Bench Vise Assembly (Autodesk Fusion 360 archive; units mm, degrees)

design "Bench Vice Assembly" references "Handle Bar", "Jaw Screw", "Vice Nut", "Base", "Nut", "Fixed Jaw", "Sliding Jaw", "Jaw Plate"
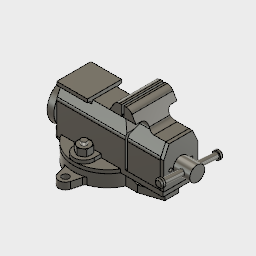
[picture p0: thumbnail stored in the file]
component_insert "Component Insert1"
ground "Ground1"
component_insert "Component Insert2"
joint "Assemble1" OffsetX 0 OffsetY 0 OffsetZ 0 AngleZ 0 OffsetX 0 OffsetY 0 OffsetZ 0 AngleZ 0 alignAngle 0 alignOffsetX 0 alignOffsetY 0 alignOffsetZ 0
component_insert "Component Insert3"
joint "Assemble2" OffsetX 0 OffsetY 0 OffsetZ 0 AngleZ 0 OffsetX 0 OffsetY 0 OffsetZ 0 AngleZ 0 alignAngle 0 alignOffsetX 0 alignOffsetY 0 alignOffsetZ 0 DistanceMinimum -30 DistanceMaximum -2
component_insert "Component Insert4"
position "Position1"
joint "Assemble3" OffsetX 0 OffsetY 0 OffsetZ 0 AngleZ 0 OffsetX 0 OffsetY 0 OffsetZ 0 AngleZ 0 alignAngle 0 alignOffsetX 0 alignOffsetY 0 alignOffsetZ 0
component_insert "Component Insert5"
joint "Assemble4" OffsetX 0 OffsetY 0 OffsetZ 0 AngleZ 0 OffsetX 0 OffsetY 0 OffsetZ 0 AngleZ 0 alignAngle 0 alignOffsetX 0 alignOffsetY 0 alignOffsetZ 0
component_insert "Component Insert6"
joint "Assemble5" OffsetX 0 OffsetY 0 OffsetZ 0 AngleZ 0 OffsetX 0 OffsetY 0 OffsetZ 0 AngleZ 0 alignAngle 0 alignOffsetX 0 alignOffsetY 0 alignOffsetZ 0
position "Position2"
joint "Assemble6" OffsetX 0 OffsetY 0 OffsetZ 0 AngleZ 0 OffsetX 0 OffsetY 0 OffsetZ 0 AngleZ 0 alignAngle 0 alignOffsetX 0 alignOffsetY 0 alignOffsetZ 0
component_insert "Component Insert7"
position "Position3"
joint "Assemble7" OffsetX 0 OffsetY 0 OffsetZ 0 AngleZ 0 OffsetX 0 OffsetY 0 OffsetZ 0 AngleZ 0 alignAngle 0 alignOffsetX 0 alignOffsetY 0 alignOffsetZ 0
component_insert "Component Insert8"
joint "Assemble8" OffsetX 0 OffsetY 0 OffsetZ 0 AngleZ 0 OffsetX 0 OffsetY 0 OffsetZ 0 AngleZ 0 alignAngle 0 alignOffsetX 0 alignOffsetY 0 alignOffsetZ 0
component_insert "Component Insert9"
joint "Assemble9" OffsetX 0 OffsetY 0 OffsetZ 0 AngleZ 0 OffsetX 0 OffsetY 0 OffsetZ 0 AngleZ 0 alignAngle 0 alignOffsetX 0 alignOffsetY 0 alignOffsetZ 0

design "Jaw Screw"
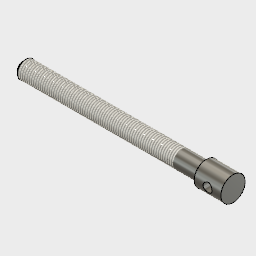
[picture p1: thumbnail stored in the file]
sketch "Sketch1" plane through (0, 0, 0) normal (1, 0, 0) x axis (0, 0, -1)
  circle C1 centre (0, 0) radius 8
  dimension "d1" diameter C1 = 16
extrude "Extrude1" new body sketch "Sketch1" distance 165
sketch "Sketch2" plane through (82.5, 0, 0) normal (1, 0, 0) x axis (0, 0, -1)
  circle C1 centre (0, 0) radius 8
  circle C2 centre (0, 0) radius 11
  dimension "d4" diameter C2 = 22
extrude "Extrude2" add sketch "Sketch2" along normal blind 24
sketch "Sketch3"
sketch "Sketch4"
  line L1 (82.5, 11) -> (82.5, -11)
  line L2 (123.0204, 0) -> (0, 0)
  line L3 (106.5, 11) -> (106.5, -11)
  circle C1 centre (94.5, 0) radius 4
  point P6 (94.5, 0)
  dimension "d7" diameter C1 = 8
  dimension "d8" distance P6 L3 = 12
extrude "Extrude3" cut sketch "Sketch4" profile of C1 no distance stored
chamfer "Chamfer1" distance 3 rotateAngle 45
thread "Thread1" ThreadOffset 0 ThreadLength 140

design "Jaw Plate"
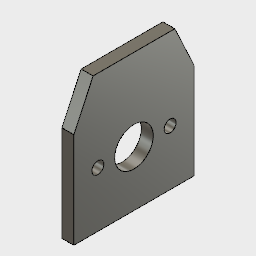
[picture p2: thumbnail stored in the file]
sketch "Sketch1" plane through (0, 0, 0) normal (1, 0, 0) x axis (0, 0, -1)
  line L1 (0, 43.6951) -> (0, 0)
  line L2 (-25, 39.8439) -> (-25, 0)
  line L3 (-17, 57) -> (-25, 39.8439)
  line L4 (17, 57) -> (-17, 57)
  line L5 (25, 39.8439) -> (17, 57)
  line L6 (25, 0) -> (25, 39.8439)
  line L7 (-25, 0) -> (25, 0)
  point P4 (-25, 0)
  point P9 (25, 0)
  point P6 (-17, 57)
  point P7 (17, 57)
  dimension "d1" distance P4 P9 = 50
  dimension "d2" distance P6 P7 = 34
  dimension "d3" distance L4 L7 = 57
  dimension "d4" angle L2 L3 = 25
extrude "Extrude1" new body sketch "Sketch1" profile of L2 L3 L4 L5 L6 L7 along normal blind 5
sketch "Sketch2" plane through (5, 0, 0) normal (1, 0, 0) x axis (0, 0, -1)
  line L1 (25, 39.8439) -> (25, 0)
  line L2 (17, 57) -> (25, 39.8439)
  line L3 (-17, 57) -> (17, 57)
  line L4 (-25, 39.8439) -> (-17, 57)
  line L5 (-25, 0) -> (-25, 39.8439)
  line L6 (25, 0) -> (-25, 0)
  line L7 (0, 50.8818) -> (0, 0)
  circle C1 centre (0, 23) radius 8
  circle C2 centre (0, 23) radius 15
  circle C3 centre (-15, 23) radius 2.5
  circle C4 centre (15, 23) radius 2.5
  point P1 (0, 0)
  point P10 (0, 23)
  dimension "d7" distance P1 P10 = 23
  dimension "d8" diameter C1 = 16
  dimension "d9" diameter C2 = 30
  dimension "d10" diameter C3 = 5
extrude "Extrude2" cut sketch "Sketch2" profile of C1 C3 C4 no distance stored

design "Fixed Jaw"
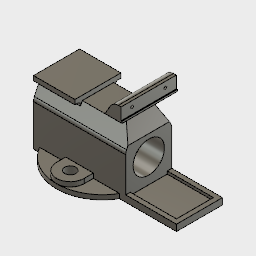
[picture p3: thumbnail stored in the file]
sketch "Sketch1" plane through (0, 0, 0) normal (0, 1, 0) x axis (1, 0, 0)
  circle C1 centre (0, 0) radius 50
  dimension "d1" diameter C1 = 100
extrude "Extrude1" new body sketch "Sketch1" along normal blind 5
sketch "Sketch2" plane through (0, 5, 0) normal (0, 1, 0) x axis (-1, 0, 0)
  line L1 (-15, -35) -> (-15, 35)
  line L2 (15, 35) -> (15, -35)
  line L3 (0, -35) -> (0, 35)
  circle C1 centre (0, 0) radius 50
  arc A1 centre (0, -35) radius 15 clockwise from (15, -35) to (-15, -35)
  arc A2 centre (0, 35) radius 15 clockwise from (-15, 35) to (15, 35)
  point P7 (0, 35)
  point P8 (0, -35)
  dimension "d4" radius A1 = 15
  dimension "d5" distance P7 P8 = 70
extrude "Extrude2" add sketch "Sketch2" profile of L1 A1 L2 A2 along normal blind 5
sketch "Sketch3" plane through (0, 10, 0) normal (0, 1, 0) x axis (-1, 0, 0)
  line L1 (-15, -35) -> (-15, 35)
  line L2 (15, 35) -> (15, -35)
  arc A1 centre (0, 35) radius 15 clockwise from (-15, 35) to (15, 35)
  arc A2 centre (0, -35) radius 15 clockwise from (15, -35) to (-15, -35)
  circle C1 centre (0, 35) radius 6
  circle C2 centre (0, -35) radius 6
  dimension "d8" diameter C2 = 12
extrude "Extrude3" cut sketch "Sketch3" profile of C1 C2 no distance stored
sketch "Sketch4" plane through (0, 0, 0) normal (1, 0, 0) x axis (0, 0, -1)
  line L1 (-50, 5) -> (50, 5)
  line L2 (0, 55.8239) -> (0, 0)
  line L3 (-50, 0) -> (50, 0)
  line L4 (-25, 46.8439) -> (-25, 0)
  line L5 (-17, 64) -> (-25, 46.8439)
  line L6 (17, 64) -> (-17, 64)
  line L7 (25, 46.8439) -> (17, 64)
  line L8 (25, 0) -> (25, 46.8439)
  line L9 (25, 0) -> (-25, 0)
  point P10 (-17, 64)
  point P11 (17, 64)
  dimension "d10" distance L4 L8 = 50
  dimension "d11" distance L6 L9 = 64
  dimension "d12" distance P10 P11 = 34
  dimension "d13" angle L4 L5 = 25
extrude "Extrude4" add sketch "Sketch4" profile of L1 L3 L4 L5 L6 L7 L8 L9 distance 100
fillet "Fillet1" radius 10
sketch "Sketch5" plane through (-50, 0, 0) normal (-1, 0, 0) x axis (0, 0, 1)
  line L1 (-25, 0) -> (-25, 44.627)
  line L2 (25, 0) -> (-25, 0)
  line L3 (25, 44.627) -> (25, 0)
  line L4 (17, 64) -> (24.0631, 48.8532)
  line L5 (-17, 64) -> (17, 64)
  line L6 (-24.0631, 48.8532) -> (-17, 64)
  line L7 (0, 78.169) -> (0, 0)
  line L8 (25, 69) -> (-25, 69)
  line L9 (25, 64) -> (25, 69)
  line L10 (-25, 64) -> (25, 64)
  line L11 (-25, 69) -> (-25, 64)
  arc A1 centre (-15, 44.627) radius 10 clockwise from (-25, 44.627) to (-24.0631, 48.8532)
  arc A2 centre (15, 44.627) radius 10 clockwise from (24.0631, 48.8532) to (25, 44.627)
  point P14 (-25, 69)
  point P15 (25, 69)
  point P17 (-25, 64)
  dimension "d17" distance P14 P15 = 50
  dimension "d18" distance P14 P17 = 5
extrude "Extrude5" add sketch "Sketch5" profile of L5 L8 L9 L10 L11 against normal blind 45
fillet "Fillet2" radius 3
sketch "Sketch6" plane through (50, 0, 0) normal (1, 0, 0) x axis (0, 0, -1)
  line L1 (17, 64) -> (24.0631, 48.8532)
  line L2 (-17, 64) -> (17, 64)
  line L3 (-24.0631, 48.8532) -> (-17, 64)
  line L4 (-25, 0) -> (-25, 44.627)
  line L5 (25, 0) -> (-25, 0)
  line L6 (25, 44.627) -> (25, 0)
  line L7 (25, 0) -> (-25, 0)
  line L8 (25, 7) -> (25, 0)
  line L9 (-25, 7) -> (25, 7)
  line L10 (-25, 0) -> (-25, 7)
  arc A1 centre (15, 44.627) radius 10 clockwise from (24.0631, 48.8532) to (25, 44.627)
  arc A2 centre (-15, 44.627) radius 10 clockwise from (-25, 44.627) to (-24.0631, 48.8532)
  point P13 (25, 0)
  point P14 (25, 7)
  dimension "d22" distance P13 P14 = 7
extrude "Extrude6" add sketch "Sketch6" profile of L4 L5 L6 L7 L8 L9 L10 along normal blind 55
sketch "Sketch7"
  line L1 (50, 64) -> (-5, 64)
  line L2 (50, 92) -> (50, 64)
  line L3 (47, 92) -> (50, 92)
  line L4 (25.0607, 64) -> (38.3397, 87)
  line L5 (25.0607, 64) -> (50, 64)
  arc A1 centre (47, 82) radius 10 clockwise from (38.3397, 87) to (47, 92)
  point P5 (50, 64)
  point P6 (50, 92)
  point P7 (47, 92)
  dimension "d25" distance P5 P6 = 28
  dimension "d26" distance P6 P7 = 3
  dimension "d27" radius A1 = 10
  dimension "d28" angle L1 L4 = 120
extrude "Extrude7" add sketch "Sketch7" distance 60
sketch "Sketch8" plane through (0, 0, 30) normal (0, 0, 1) x axis (1, 0, 0)
  line L1 (47, 92) -> (50, 92)
  line L2 (25.0607, 64) -> (38.3397, 87)
  line L3 (50, 64) -> (25.0607, 64)
  line L4 (50, 92) -> (50, 64)
  line L5 (44.2265, 77) -> (50, 77)
  line L6 (50, 64) -> (50, 48.8532)
  line L7 (50, 52) -> (39.8964, 69.5)
  line L8 (50, 77) -> (50, 52)
  arc A1 centre (47, 82) radius 10 clockwise from (38.3397, 87) to (47, 92)
  arc A2 centre (44.2265, 72) radius 5 clockwise from (39.8964, 69.5) to (44.2265, 77)
  point P14 (50, 52)
  dimension "d31" distance L1 L5 = 15
  dimension "d32" distance L1 P14 = 40
  dimension "d33" radius A2 = 5
  dimension "d34" angle L7 L8 = 30
extrude "Extrude8" cut sketch "Sketch8" profile of L3 L4 L5 A2 L6 L7 L8 no distance stored
sketch "Sketch9" plane through (50, 0, 0) normal (1, 0, 0) x axis (0, 0, -1)
  line L1 (30, 77) -> (-30, 77)
  line L2 (30, 92) -> (30, 77)
  line L3 (-30, 92) -> (30, 92)
  line L4 (-30, 77) -> (-30, 92)
  line L5 (-21.9258, 77) -> (-30, 77)
  line L6 (-30, 36.1214) -> (-15.5816, 67.0417)
  line L7 (-30, 77) -> (-30, 36.1214)
  line L8 (-30, 69.5) -> (-30, 64)
  line L9 (-17, 64) -> (-22.5957, 52)
  arc A1 centre (-21.9258, 70) radius 7 clockwise from (-21.9258, 77) to (-15.5816, 67.0417)
  dimension "d36" radius A1 = 7
extrude "Extrude9" cut sketch "Sketch9" profile of L1 L5 A1 L6 L7 L8 L9 to an object
mirror "Mirror1"
sketch "Sketch10" plane through (50, 0, 0) normal (1, 0, 0) x axis (0, 0, -1)
  line L1 (30, 77) -> (-30, 77)
  line L2 (30, 92) -> (30, 77)
  line L3 (-30, 92) -> (30, 92)
  line L4 (-30, 77) -> (-30, 92)
  line L5 (30, 77) -> (-30, 77)
  line L6 (30, 79) -> (30, 77)
  line L7 (-30, 79) -> (30, 79)
  line L8 (-30, 77) -> (-30, 79)
  point P7 (30, 77)
  point P8 (30, 79)
  dimension "d40" distance P7 P8 = 2
extrude "Extrude10" add sketch "Sketch10" profile of L1 L2 L4 L5 L6 L7 L8 along normal blind 1
sketch "Sketch11" plane through (50, 0, 0) normal (1, 0, 0) x axis (0, 0, -1)
  line L1 (-22.5957, 52) -> (22.5957, 52)
  line L2 (-24.0631, 48.8532) -> (-22.5957, 52)
  line L3 (-25, 7) -> (-25, 44.627)
  line L4 (25, 7) -> (-25, 7)
  line L5 (25, 44.627) -> (25, 7)
  line L6 (22.5957, 52) -> (24.0631, 48.8532)
  line L7 (0, 42.1185) -> (0, 0)
  arc A1 centre (-15, 44.627) radius 10 clockwise from (-25, 44.627) to (-24.0631, 48.8532)
  arc A2 centre (15, 44.627) radius 10 clockwise from (24.0631, 48.8532) to (25, 44.627)
  circle C1 centre (0, 30) radius 17
  point P1 (0, 0)
  point P14 (0, 30)
  dimension "d43" diameter C1 = 34
  dimension "d44" distance P1 P14 = 30
extrude "Extrude11" cut sketch "Sketch11" profile of C1 no distance stored
sketch "Sketch12" plane through (50, 0, 0) normal (1, 0, 0) x axis (0, 0, -1)
  line L1 (30, 79) -> (-30, 79)
  line L2 (30, 92) -> (30, 79)
  line L3 (-30, 92) -> (30, 92)
  line L4 (-30, 79) -> (-30, 92)
  line L5 (-30, 87) -> (30, 87)
  line L6 (0, 104.4277) -> (0, 0)
  circle C1 centre (-18, 86) radius 1.5
  circle C2 centre (18, 86) radius 1.5
  point P6 (-18, 86)
  point P9 (18, 86)
  dimension "d46" diameter C1 = 3
  dimension "d47" distance P6 P9 = 36
  dimension "d48" distance L3 P6 = 6
extrude "Extrude12" cut sketch "Sketch12" profile of C1 L5 C2 against normal blind 5
sketch "Sketch13" plane through (0, 7, 0) normal (0, 1, 0) x axis (-1, 0, 0)
  line L1 (-50, 25) -> (-50, -25)
  line L2 (-105, 25) -> (-50, 25)
  line L3 (-105, -25) -> (-105, 25)
  line L4 (-50, -25) -> (-105, -25)
  line L5 (-100, 20) -> (-50, 20)
  line L6 (-100, -20) -> (-100, 20)
  line L7 (-50, -20) -> (-100, -20)
  dimension "d51" = 5
extrude "Extrude13" cut sketch "Sketch13" profile of L1 L5 L6 L7 against normal blind 3
fillet "Fillet3" radius 10
sketch "Sketch14" plane through (-50, 0, 0) normal (-1, 0, 0) x axis (0, 0, 1)
  line L1 (-25, 0) -> (-25, 44.627)
  line L2 (25, 0) -> (-25, 0)
  line L3 (25, 44.627) -> (25, 0)
  line L4 (18.9901, 59.7321) -> (24.0631, 48.8532)
  line L5 (25, 64) -> (21.7091, 64)
  line L6 (25, 69) -> (25, 64)
  line L7 (-25, 69) -> (25, 69)
  line L8 (-25, 64) -> (-25, 69)
  line L9 (-21.7091, 64) -> (-25, 64)
  line L10 (-24.0631, 48.8532) -> (-18.9901, 59.7321)
  line L11 (0, 61.9125) -> (0, 0)
  circle C1 centre (0, 30) radius 17
  arc A1 centre (-15, 44.627) radius 10 clockwise from (-25, 44.627) to (-24.0631, 48.8532)
  arc A2 centre (15, 44.627) radius 10 clockwise from (24.0631, 48.8532) to (25, 44.627)
  arc A3 centre (21.7091, 61) radius 3 clockwise from (18.9901, 59.7321) to (21.7091, 64)
  arc A4 centre (-21.7091, 61) radius 3 clockwise from (-21.7091, 64) to (-18.9901, 59.7321)
  circle C2 centre (0, 52.5) radius 2.5
  circle C3 centre (0, 7.5) radius 2.5
  circle C4 centre (0, 30) radius 22.5
  dimension "d55" diameter C2 = 5
  dimension "d56" diameter C4 = 45
extrude "Extrude14" cut sketch "Sketch14" profile of C2 C3 against normal blind 10

design "Handle Bar"
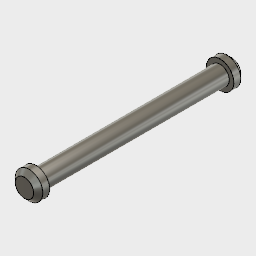
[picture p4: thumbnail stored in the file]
sketch "Sketch1"
  circle C1 centre (0, 0) radius 4
  dimension "d1" diameter C1 = 8
extrude "Extrude1" new body sketch "Sketch1" distance 80
sketch "Sketch2" plane through (0, 0, 40) normal (0, 0, 1) x axis (1, 0, 0)
  circle C1 centre (0, 0) radius 4
  circle C2 centre (0, 0) radius 6
  dimension "d4" diameter C2 = 12
extrude "Extrude2" add sketch "Sketch2" along normal blind 5
chamfer "Chamfer1" distance 2 rotateAngle 45
mirror "Mirror1"

design "Vice Nut"
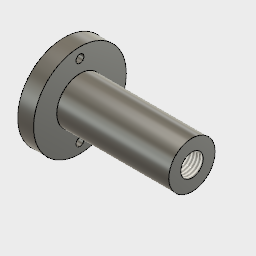
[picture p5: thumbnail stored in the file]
sketch "Sketch1" plane through (0, 0, 0) normal (1, 0, 0) x axis (0, 0, -1)
  circle C1 centre (0, 0) radius 14.5
  dimension "d1" diameter C1 = 29
extrude "Extrude1" new body sketch "Sketch1" along normal blind 70
sketch "Sketch2" plane through (0, 0, 0) normal (-1, 0, 0) x axis (0, 0, 1)
  circle C1 centre (0, 0) radius 14.5
  circle C2 centre (0, 0) radius 29
  dimension "d4" diameter C2 = 58
extrude "Extrude2" add sketch "Sketch2" along normal blind 10
sketch "Sketch3" plane through (-10, 0, 0) normal (-1, 0, 0) x axis (0, 0, 1)
  circle C1 centre (0, 0) radius 29
  circle C2 centre (0, 0) radius 13
  dimension "d7" diameter C2 = 26
extrude "Extrude3" cut sketch "Sketch3" profile of C2 against normal blind 48
sketch "Sketch4" plane through (70, 0, 0) normal (1, 0, 0) x axis (0, 0, -1)
  circle C1 centre (0, 0) radius 14.5
  circle C2 centre (0, 0) radius 8
  dimension "d10" diameter C2 = 16
extrude "Extrude4" cut sketch "Sketch4" profile of C2 no distance stored
chamfer "Chamfer1" distance 4 rotateAngle 45
sketch "Sketch5" plane through (0, 0, 0) normal (1, 0, 0) x axis (0, 0, -1)
  line L1 (0, -34.1673) -> (0, 33.8255)
  circle C1 centre (0, 0) radius 29
  circle C2 centre (0, 0) radius 14.5
  circle C3 centre (0, 0) radius 22.5
  circle C4 centre (0, 22.5) radius 2.5
  circle C5 centre (0, -22.5) radius 2.5
  dimension "d14" diameter C3 = 45
  dimension "d15" diameter C4 = 5
extrude "Extrude5" cut sketch "Sketch5" profile of C4 C5 no distance stored
thread "Thread1"

design "Nut"
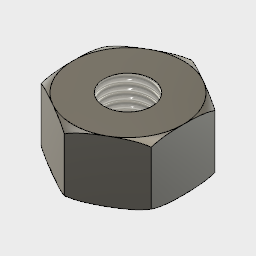
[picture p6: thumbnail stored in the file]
sketch "Sketch1" plane through (0, 0, 0) normal (0, 1, 0) x axis (1, 0, 0)
  line L1 (-9, 5.1962) -> (0, 10.3923)
  line L2 (-9, -5.1962) -> (-9, 5.1962)
  line L3 (0, -10.3923) -> (-9, -5.1962)
  line L4 (9, -5.1962) -> (0, -10.3923)
  line L5 (9, 5.1962) -> (9, -5.1962)
  line L6 (0, 10.3923) -> (9, 5.1962)
  circle C1 centre (0, 0) radius 4.5
  dimension "d1" distance L2 L5 = 18
  dimension "d2" diameter C1 = 9
extrude "Extrude1" new body sketch "Sketch1" distance 10
sketch "Sketch3"
  line L1 (9, 5) -> (9, -5)
  line L2 (12, 5) -> (9, 5)
  line L3 (12, 2) -> (12, 5)
  line L4 (4.5, -5) -> (-4.5, -5)
  line L5 (0, 13.044) -> (0, 0)
  arc A1 centre (8.1021, 1.1021) radius 4 clockwise from (9, 5) to (12, 2)
  point P4 (9, 5)
  point P5 (12, 5)
  dimension "d6" distance P4 P5 = 3
  dimension "d7" radius A1 = 4
revolve "Revolve1" sketch "Sketch3" AlongAngle 360
mirror "Mirror1"
thread "Thread1"

design "Base"
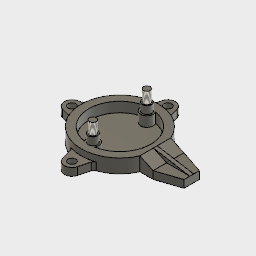
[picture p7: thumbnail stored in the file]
sketch "Sketch1" plane through (0, 0, 0) normal (0, 1, 0) x axis (1, 0, 0)
  circle C1 centre (0, 0) radius 50
  dimension "d1" diameter C1 = 100
extrude "Extrude1" new body sketch "Sketch1" along normal blind 18
sketch "Sketch2" plane through (0, 18, 0) normal (0, 1, 0) x axis (-1, 0, 0)
  circle C1 centre (0, 0) radius 50
  circle C2 centre (0, 0) radius 40
  dimension "d4" diameter C2 = 80
extrude "Extrude2" cut sketch "Sketch2" profile of C2 against normal blind 13
sketch "Sketch3" plane through (0, 18, 0) normal (0, 1, 0) x axis (-1, 0, 0)
  line L1 (-95.7683, 0) -> (0, 0)
  line L2 (-63, -20) -> (-45.8258, -20)
  line L3 (-93, -10) -> (-63, -20)
  line L4 (-93, 10) -> (-93, -10)
  line L5 (-63, 20) -> (-93, 10)
  line L6 (-45.8258, 20) -> (-63, 20)
  circle C1 centre (0, 0) radius 40
  circle C2 centre (0, 0) radius 50
  circle C3 centre (0, 0) radius 50
  point P1 (0, 0)
  point P7 (-93, -10)
  point P8 (-93, 10)
  point P6 (-63, -20)
  dimension "d7" distance P1 L4 = 93
  dimension "d8" distance L2 L6 = 40
  dimension "d9" distance P7 P8 = 20
  dimension "d10" distance P6 P7 = 30
extrude "Extrude3" add sketch "Sketch3" profile of C2 C3 L2 L3 L4 L5 L6 to an object
sketch "Sketch4"
  line L1 (63, 0) -> (63, 18)
  line L2 (63, 10) -> (45.8258, 18)
  line L3 (93, 0) -> (93, 18)
  line L4 (93, 10) -> (63, 10)
  line L5 (93, 18) -> (93, 10)
  line L6 (45.8258, 18) -> (93, 18)
  line L7 (93, 0) -> (63, 0)
  dimension "d13" distance L4 L7 = 10
extrude "Extrude4" cut sketch "Sketch4" profile of L1 L2 L3 L4 L5 L6 no distance stored
sketch "Sketch5"
  line L1 (93, 10) -> (45.8258, 18)
step "Rib" Thickness 5
sketch "Sketch6" plane through (0, 18, 0) normal (0, 1, 0) x axis (-1, 0, 0)
  line L1 (-45.8258, 2.5) -> (-45.8258, 20)
  line L2 (-45.8258, -2.5) -> (-45.8258, 2.5)
  line L3 (-45.8258, -20) -> (-45.8258, -2.5)
  line L4 (-45.8258, 2.5) -> (-93, 2.5)
  line L5 (85.156, 0) -> (0, 0)
  line L6 (0, 59.7587) -> (0, -56.3092)
  arc A1 centre (0, 0) radius 50 clockwise from (-45.8258, 20) to (-45.8258, -20)
  circle C1 centre (0, 0) radius 40
  circle C2 centre (0, -35) radius 8
  circle C3 centre (0, 35) radius 8
  point P1 (0, 0)
  point P13 (0, -35)
  dimension "d17" diameter C2 = 16
  dimension "d18" distance P1 P13 = 35
extrude "Extrude5" add sketch "Sketch6" profile of C1 C2 C3 to an object
sketch "Sketch7" plane through (0, 18, 0) normal (0, 1, 0) x axis (-1, 0, 0)
  line L1 (-45.8258, 2.5) -> (-45.8258, 20)
  line L2 (-45.8258, -2.5) -> (-45.8258, 2.5)
  line L3 (-45.8258, -20) -> (-45.8258, -2.5)
  arc A1 centre (0, 0) radius 50 clockwise from (-45.8258, 20) to (-45.8258, -20)
  circle C1 centre (0, 35) radius 6
  circle C2 centre (0, -35) radius 6
  arc A2 centre (0, 0) radius 40 clockwise from (6.6529, 39.4429) to (6.6529, -39.4429)
  arc A3 centre (0, -35) radius 8 clockwise from (-6.6529, -39.4429) to (6.6529, -39.4429)
  arc A4 centre (0, 0) radius 40 clockwise from (-6.6529, -39.4429) to (-6.6529, 39.4429)
  arc A5 centre (0, 35) radius 8 clockwise from (6.6529, 39.4429) to (-6.6529, 39.4429)
  dimension "d22" diameter C2 = 12
extrude "Extrude6" add sketch "Sketch7" profile of C1 C2 along normal blind 10
sketch "Sketch8" plane through (0, 28, 0) normal (0, 1, 0) x axis (-1, 0, 0)
  circle C1 centre (0, 35) radius 6
  circle C2 centre (0, 35) radius 4.5
  circle C3 centre (0, -35) radius 4.5
  circle C4 centre (0, -35) radius 6
  dimension "d25" diameter C3 = 9
extrude "Extrude7" add sketch "Sketch8" profile of C2 C3 along normal blind 15
thread "Thread1"
thread "Thread2"
sketch "Sketch9" plane through (0, 0, 0) normal (0, -1, 0) x axis (1, 0, 0)
  line L1 (93, 10) -> (93, -10)
  line L2 (63, 20) -> (93, 10)
  line L3 (45.8258, 20) -> (63, 20)
  line L4 (63, -20) -> (45.8258, -20)
  line L5 (93, -10) -> (63, -20)
  line L6 (-54.8103, 0) -> (0, 0)
  line L7 (0, 62.7215) -> (0, 0)
  line L8 (-64.5882, 9.6593) -> (-47.9669, 14.1129)
  line L9 (-47.9669, -14.1129) -> (-64.5882, -9.6593)
  arc A1 centre (0, 0) radius 50 clockwise from (45.8258, -20) to (45.8258, 20)
  arc A2 centre (0, 0) radius 50 clockwise from (45.8258, -20) to (45.8258, 20)
  arc A3 centre (-62, 0) radius 10 clockwise from (-64.5882, -9.6593) to (-64.5882, 9.6593)
  circle C1 centre (-62, 0) radius 5
  point P18 (-62, 0)
  dimension "d28" radius A3 = 10
  dimension "d29" distance L7 P18 = 62
  dimension "d30" angle L8 L9 = 30
  dimension "d31" diameter C1 = 10
extrude "Extrude8" add sketch "Sketch9" profile of A1 A2 L8 A3 L9 C1 against normal blind 10
circular_pattern "C-Pattern1" TotalAngle 360
fillet "Fillet1" radius 5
